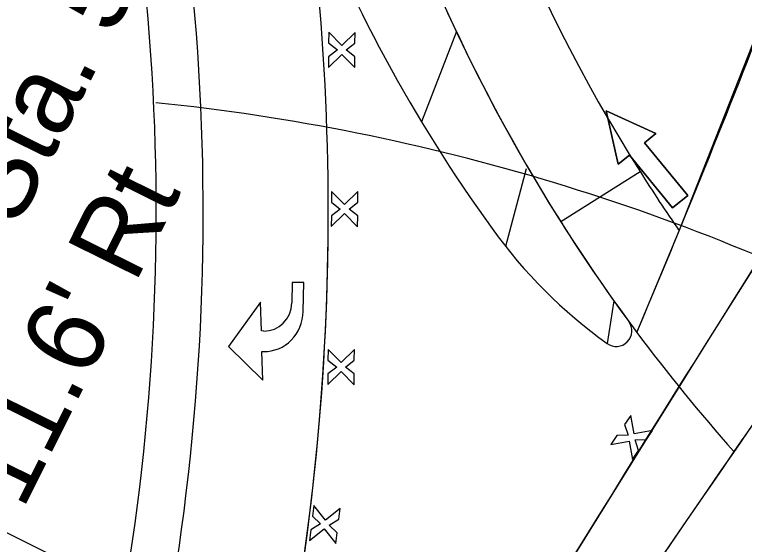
# Model space of a CAD drawing. Extents: x 14104283 to 14129344, y 8637090 to 8673339.
# Drawn here: x 14118973.5 to 14119066.9, y 8668775.1 to 8668842.9 of the extents above; entities that cross this region are included whole.
import ezdxf

# ---------------------------------------------------------------- set-up
doc = ezdxf.new("R2010")
doc.units = 0
for name, color, linetype in [('Cell', 7, 'Continuous'), ('dsnNonPlotable', 7, 'Continuous'), ('dsnPaintExistingBrokenLaneLineWhite', 7, 'Continuous'), ('dsnPaintExistingChannelizingLaneWhite', 7, 'Continuous'), ('dsnPaintExistingChannelizingLaneYellow', 7, 'Continuous'), ('dsnPaintExistingEdgeLineRightWhite', 7, 'Continuous'), ('dsnShadingPaved', 7, 'Continuous'), ('dsnStdLabel', 7, 'Continuous'), ('dsnStgShadingPrevPav', 7, 'Continuous'), ('dsnTapeExistingChannelizingLaneWhite', 7, 'Continuous'), ('dsnTapePlaceChannelizingLaneYellow', 7, 'Continuous'), ('dsnTapeRemoveChannelizingYellow', 7, 'Continuous'), ('Level 2', 7, 'Continuous'), ('Level 5', 7, 'Continuous')]:
    doc.layers.add(name, color=color, linetype=linetype)

msp = doc.modelspace()

# ---------------------------------------------------------------- linework, layer by layer
at = {"layer": 'Cell'}
for p, q in [((14119013.696, 8668840.65), (14119013.686, 8668839.275)), ((14119015.371, 8668838.949), (14119013.696, 8668840.65)), ((14119017.071, 8668840.623), (14119015.371, 8668838.949)), ((14119017.06, 8668839.248), (14119017.071, 8668840.623)), ((14119013.686, 8668839.275), (14119014.804, 8668838.391)), ((14119015.929, 8668838.382), (14119017.06, 8668839.248)), ((14119013.661, 8668836.15), (14119015.362, 8668837.824)), ((14119014.804, 8668838.391), (14119013.672, 8668837.525)), ((14119015.362, 8668837.824), (14119017.036, 8668836.123)), ((14119017.047, 8668837.498), (14119015.929, 8668838.382)), ((14119013.672, 8668837.525), (14119013.661, 8668836.15)), ((14119017.036, 8668836.123), (14119017.047, 8668837.498)), ((14119014.063, 8668820.28), (14119014.053, 8668818.905)), ((14119015.737, 8668818.579), (14119014.063, 8668820.28)), ((14119017.438, 8668820.253), (14119015.737, 8668818.579)), ((14119017.427, 8668818.878), (14119017.438, 8668820.253)), ((14119015.171, 8668818.021), (14119014.039, 8668817.155)), ((14119014.053, 8668818.905), (14119015.171, 8668818.021)), ((14119016.296, 8668818.012), (14119017.427, 8668818.878)), ((14119017.414, 8668817.128), (14119016.296, 8668818.012)), ((14119014.028, 8668815.78), (14119015.729, 8668817.454)), ((14119014.039, 8668817.155), (14119014.028, 8668815.78)), ((14119015.729, 8668817.454), (14119017.403, 8668815.753)), ((14119017.403, 8668815.753), (14119017.414, 8668817.128)), ((14119005.403, 8668802.4), (14119005.089, 8668802.408)), ((14119005.16, 8668799.777), (14119005.343, 8668799.773)), ((14119013.613, 8668800.053), (14119013.602, 8668798.678)), ((14119015.287, 8668798.352), (14119013.613, 8668800.053)), ((14119016.988, 8668800.026), (14119015.287, 8668798.352)), ((14119016.977, 8668798.651), (14119016.988, 8668800.026)), ((14119013.602, 8668798.678), (14119014.72, 8668797.794)), ((14119015.845, 8668797.785), (14119016.977, 8668798.651)), ((14119014.72, 8668797.794), (14119013.589, 8668796.928)), ((14119016.963, 8668796.901), (14119015.845, 8668797.785)), ((14119013.578, 8668795.553), (14119015.278, 8668797.227)), ((14119013.589, 8668796.928), (14119013.578, 8668795.553)), ((14119015.278, 8668797.227), (14119016.953, 8668795.526)), ((14119016.953, 8668795.526), (14119016.963, 8668796.901)), ((14119052.327, 8668791.579), (14119051.548, 8668790.446)), ((14119052.761, 8668789.232), (14119052.327, 8668791.579)), ((14119051.548, 8668790.446), (14119051.979, 8668789.087)), ((14119051.979, 8668789.087), (14119050.556, 8668789.004)), ((14119055.108, 8668789.665), (14119052.761, 8668789.232)), ((14119054.328, 8668788.533), (14119055.108, 8668789.665)), ((14119050.556, 8668789.004), (14119049.776, 8668787.872)), ((14119049.776, 8668787.872), (14119052.123, 8668788.305)), ((14119052.123, 8668788.305), (14119052.557, 8668785.958)), ((14119052.905, 8668788.45), (14119054.328, 8668788.533)), ((14119053.336, 8668787.091), (14119052.905, 8668788.45)), ((14119052.557, 8668785.958), (14119053.336, 8668787.091)), ((14119011.797, 8668780.066), (14119011.632, 8668778.701)), ((14119013.269, 8668778.187), (14119011.797, 8668780.066)), ((14119015.148, 8668779.659), (14119013.269, 8668778.187)), ((14119014.982, 8668778.294), (14119015.148, 8668779.659)), ((14119011.632, 8668778.701), (14119012.643, 8668777.697)), ((14119013.76, 8668777.561), (14119014.982, 8668778.294)), ((14119011.255, 8668775.599), (14119013.134, 8668777.071)), ((14119011.421, 8668776.964), (14119011.255, 8668775.599)), ((14119012.643, 8668777.697), (14119011.421, 8668776.964)), ((14119013.134, 8668777.071), (14119014.605, 8668775.192)), ((14119014.771, 8668776.557), (14119013.76, 8668777.561)), ((14119014.605, 8668775.192), (14119014.771, 8668776.557))]:
    msp.add_line(p, q, dxfattribs=at)
for points in [[(14119010.442, 8668804.914), (14119010.526, 8668808.593), (14119009.033, 8668808.627), (14119008.973, 8668805.999)], [(14119010.442, 8668804.914), (14119010.526, 8668808.593), (14119009.033, 8668808.627), (14119008.973, 8668805.999)], [(14119005.089, 8668802.408), (14119004.989, 8668806.09), (14119000.874, 8668800.401)], [(14119005.089, 8668802.408), (14119004.989, 8668806.09), (14119000.874, 8668800.401)], [(14119005.403, 8668802.4), (14119005.089, 8668802.408)], [(14119000.874, 8668800.401), (14119005.259, 8668796.094), (14119005.16, 8668799.777)], [(14119000.874, 8668800.401), (14119005.259, 8668796.094), (14119005.16, 8668799.777)], [(14119005.16, 8668799.777), (14119005.343, 8668799.773)]]:
    msp.add_lwpolyline(points, dxfattribs=at)
for centre, major_axis in [((14119005.487, 8668806.079), (0.084, 3.679)), ((14119005.487, 8668806.079), (0.084, 3.679)), ((14119005.463, 8668805.028), (0.12, 5.255)), ((14119005.463, 8668805.028), (0.12, 5.255))]:
    msp.add_ellipse(centre, major_axis=major_axis, ratio=0.9474, start_param=3.141593, end_param=4.712389, dxfattribs=at)
at = {"layer": 'dsnNonPlotable'}
for points in [[(14118631.637, 8668945.098), (14119326.368, 8670350.234), (14120231.75, 8669902.592), (14119537.019, 8668497.457)], [(14118855.742, 8668834.296), (14119550.473, 8670239.431), (14120003.163, 8670015.611), (14119308.433, 8668610.475)]]:
    msp.add_lwpolyline(points, close=True, dxfattribs=at)
at = {"layer": 'dsnPaintExistingBrokenLaneLineWhite'}
for centre, radius, start, end in [((14121592.114, 8667345.675), 2864.949, 147.157369, 157.163302), ((14121955.849, 8666791.923), 3500, 144.954928, 149.507619)]:
    msp.add_arc(centre, radius, start, end, dxfattribs=at)
at = {"layer": 'dsnPaintExistingChannelizingLaneWhite'}
msp.add_arc((14118697.651, 8668817.618), 316, 343.63038, 0.40763, dxfattribs=at)
at = {"layer": 'dsnPaintExistingChannelizingLaneYellow'}
for p, q in [((14119030.029, 8668840.743), (14119025.563, 8668829.193)), ((14119038.934, 8668823.154), (14119036.321, 8668813.228)), ((14119050.179, 8668806.25), (14119049.299, 8668800.807))]:
    msp.add_line(p, q, dxfattribs=at)
for centre, radius, start, end in [((14119233.616, 8668936.541), 225, 186.30423, 216.21391), ((14119196.842, 8668932.457), 200, 186.33658, 215.78022), ((14119087.322, 8668853.526), 65, 215.78022, 234.19969), ((14119050.469, 8668802.429), 2, 234.19969, 36.21391)]:
    msp.add_arc(centre, radius, start, end, dxfattribs=at)
at = {"layer": 'dsnPaintExistingEdgeLineRightWhite'}
for centre, radius, start, end in [((14121592.114, 8667345.675), 2852.949, 147.157369, 157.163302), ((14118697.651, 8668817.618), 300, 343.63038, 12.51038)]:
    msp.add_arc(centre, radius, start, end, dxfattribs=at)
at = {"layer": 'dsnShadingPaved'}
for p, q in [((14119058.527, 8668815.244), (14119075.626, 8668858.76)), ((14119043.37, 8668816.41), (14119053.517, 8668822.817)), ((14119043.37, 8668816.41), (14119053.517, 8668822.817)), ((14119053.103, 8668802.228), (14119058.527, 8668815.244))]:
    msp.add_line(p, q, dxfattribs=at)
for centre, radius, start, end in [((14119233.616, 8668936.541), 225, 167.93292, 212.27034), ((14119233.616, 8668936.541), 213, 167.93292, 212.27034), ((14119233.616, 8668936.541), 213, 167.93292, 212.27034), ((14120823.304, 8667767.54), 2012, 143.15224, 151.245378), ((14118697.651, 8668817.618), 300, 343.63038, 12.51038), ((14117682.326, 8669381.119), 1488, 337.648227, 339.448576), ((14118697.651, 8668817.618), 316, 343.63038, 6.54321), ((14119233.616, 8668936.541), 213, 212.27034, 214.71306), ((14119233.616, 8668936.541), 213, 212.27034, 214.71306), ((14119233.616, 8668936.541), 225, 212.27034, 216.65145), ((14117682.326, 8669381.119), 1488, 337.105251, 337.648228), ((14121955.849, 8666791.923), 3512, 144.954928, 152.692114), ((14121955.849, 8666791.923), 3512, 144.954928, 145.38458), ((14119233.616, 8668936.541), 225, 216.65145, 221.66466), ((14121955.849, 8666791.923), 3500, 144.954928, 152.692114)]:
    msp.add_arc(centre, radius, start, end, dxfattribs=at)
at = {"layer": 'dsnStdLabel'}
msp.add_arc((14118963.835, 8668562.033), 271.027, 62.16209, 84.12167, dxfattribs=at)
at = {"layer": 'dsnStgShadingPrevPav'}
for centre, radius, start, end in [((14123732.957, 8665874.379), 5512, 146.425624, 157.163302), ((14123732.586, 8665873.821), 5512, 146.502133, 150.361956), ((14123732.957, 8665874.379), 5488, 146.421187, 157.163302), ((14123732.846, 8665874.198), 5488.008, 146.41277, 150.668735), ((14121592.114, 8667345.675), 2888.949, 147.236664, 156.233892), ((14121592.107, 8667345.679), 2888.949, 147.236664, 155.318405), ((14121592.114, 8667345.675), 2876.949, 147.240092, 156.233892), ((14121574.889, 8667355.291), 2857.26, 147.215341, 155.938429), ((14121574.765, 8667355.067), 2854.278, 147.211046, 155.933336), ((14118697.651, 8668817.618), 294, 343.63038, 12.51038)]:
    msp.add_arc(centre, radius, start, end, dxfattribs=at)
at = {"layer": 'dsnTapeExistingChannelizingLaneWhite'}
msp.add_arc((14121955.849, 8666791.923), 3512, 145.38458, 147.963777, dxfattribs=at)
at = {"layer": 'dsnTapePlaceChannelizingLaneYellow'}
for centre, radius, start, end in [((14120823.304, 8667767.54), 2012, 143.15224, 151.245378), ((14121955.849, 8666791.923), 3500, 144.954928, 149.507619)]:
    msp.add_arc(centre, radius, start, end, dxfattribs=at)
at = {"layer": 'dsnTapeRemoveChannelizingYellow'}
msp.add_arc((14121955.849, 8666791.923), 3488, 144.954928, 149.507619, dxfattribs=at)
at = {"layer": 'Level 2'}
msp.add_lwpolyline([(14119057.678, 8668818.152), (14119059.617, 8668819.73), (14119054.091, 8668826.515), (14119055.545, 8668827.699), (14119049.175, 8668830.571), (14119050.699, 8668823.752), (14119052.153, 8668824.936)], close=True, dxfattribs=at)
at = {"layer": 'Level 5'}
msp.add_lwpolyline([(14119052.153, 8668824.936), (14119050.699, 8668823.752), (14119049.175, 8668830.571), (14119055.545, 8668827.699), (14119054.091, 8668826.515), (14119059.617, 8668819.73), (14119057.678, 8668818.152), (14119052.153, 8668824.936)], dxfattribs=at)

# ---------------------------------------------------------------- texts
at = {"layer": 'dsnStdLabel'}
for s, height, p in [('PRC Sta. 599+90.8', 9.99998, (14118959.63, 8668786.789)), ("11.6' Rt", 10, (14118974.558, 8668779.378))]:
    msp.add_text(s, height=height, rotation=63.60023, dxfattribs=at).set_placement(p)

doc.saveas('drawing.dxf')
